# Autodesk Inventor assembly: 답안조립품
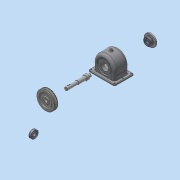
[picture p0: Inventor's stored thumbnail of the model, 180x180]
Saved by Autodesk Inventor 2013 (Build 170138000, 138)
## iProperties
Created: 2015-09
Part Number: 답안조립품
Document SubType Name: Assembly
Designer: Administrator
Author: Administrator
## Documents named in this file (6)
- C:\Users\Administrator\Desktop\450908V1032\답안조립품.iam
- C:\Users\Administrator\Desktop\450908V1032\본체.ipt
- C:\Users\Administrator\Desktop\450908V1032\축.ipt
- C:\Users\Administrator\Desktop\450908V1032\V-벨트풀리.ipt
- C:\Users\Administrator\Desktop\450908V1032\뒤커버.ipt
- C:\Users\Administrator\Desktop\450908V1032\베어링 6203.ipt
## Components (1 placed, 1 different names)
1. V-벨트풀리:1
